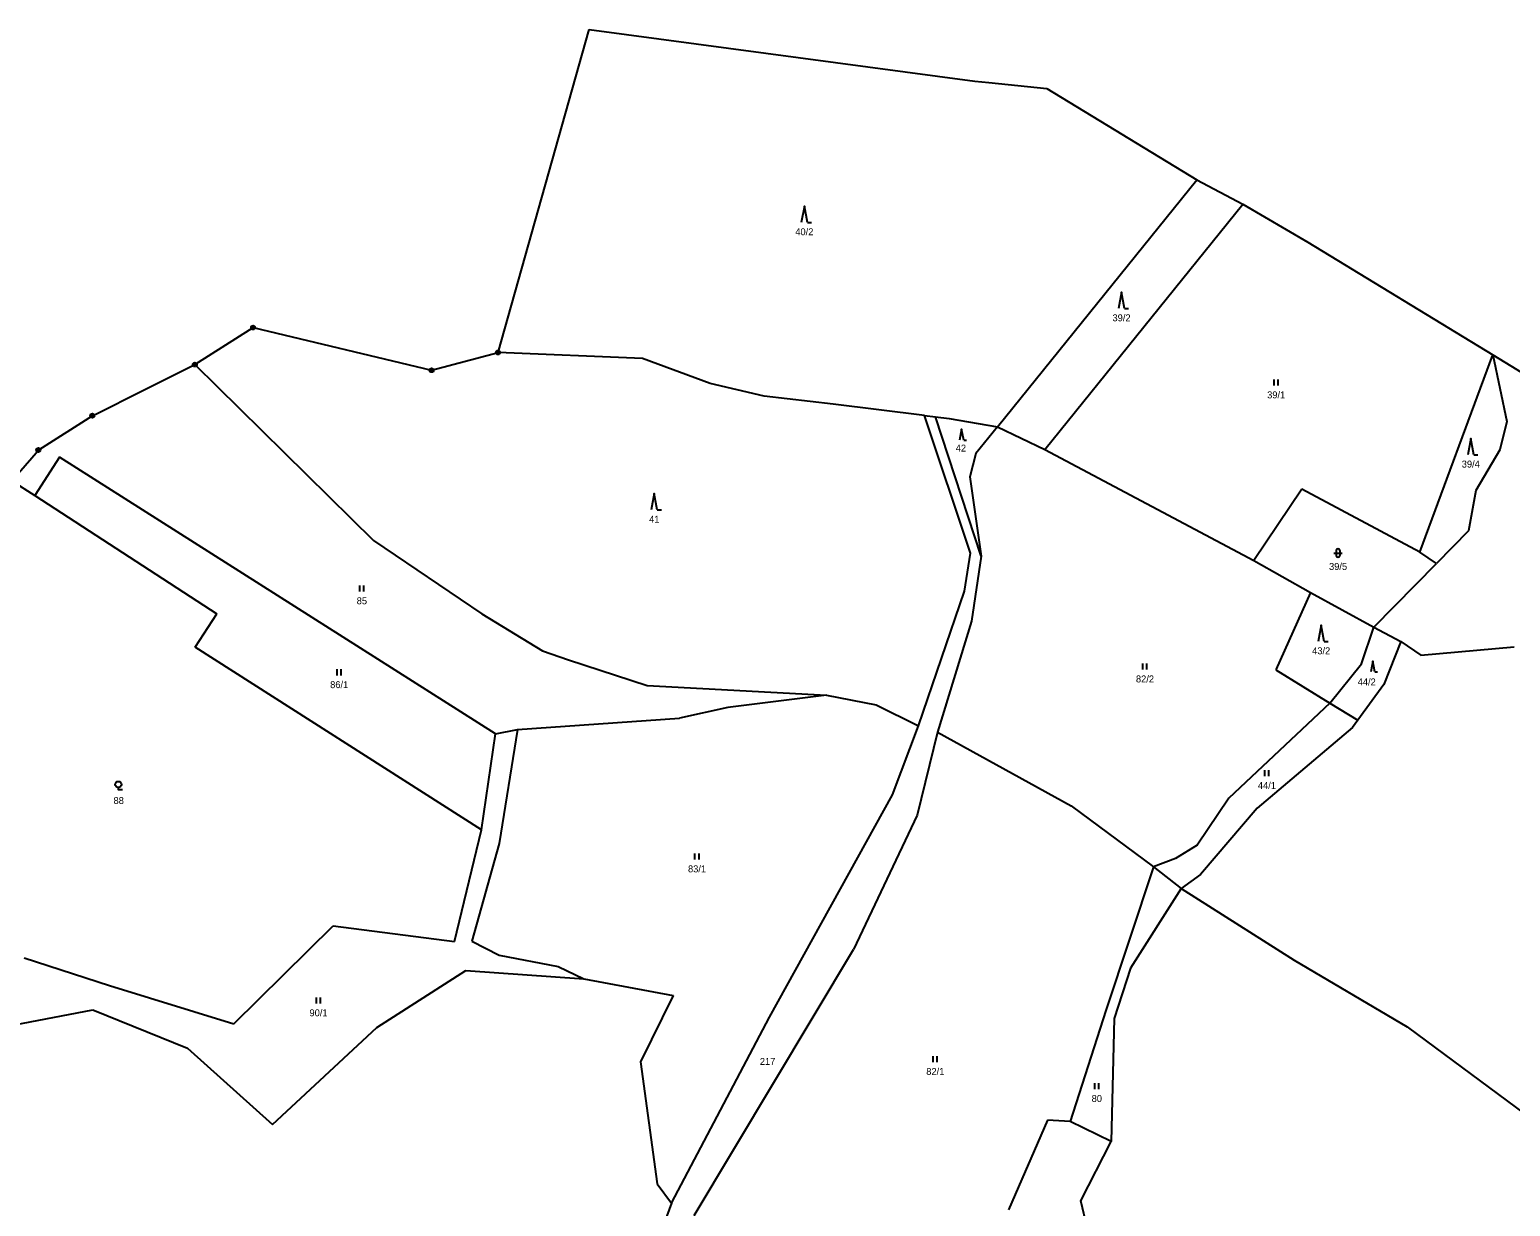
# Model space of a CAD drawing. Extents: x -601877 to -599786, y -1122905 to -1121218.
# Drawn here: x -601151.3 to -600789, y -1121506 to -1121217.8 of the extents above; entities that cross this region are included whole.
import ezdxf
from ezdxf.enums import TextEntityAlignment as Align

# ---------------------------------------------------------------- set-up
doc = ezdxf.new("R2010")
doc.units = 0
doc.header["$LTSCALE"] = 0.68
for name, color, linetype, lineweight in [('1', 7, 'Continuous', 25), ('3', 7, 'Continuous', 25), ('8', 7, 'Continuous', 25)]:
    doc.layers.add(name, color=color, linetype=linetype, lineweight=lineweight)
doc.layers.add('2', color=7, linetype='Continuous')

msp = doc.modelspace()

# ---------------------------------------------------------------- linework, layer by layer
at = {"layer": '1'}
for p, q in [((-601036.7, -1121296.89), (-601014.37, -1121217.82)), ((-601014.37, -1121217.82), (-600920.01, -1121230.46)), ((-600920.01, -1121230.46), (-600916.56, -1121230.81)), ((-600916.56, -1121230.81), (-600902.43, -1121232.26)), ((-600902.43, -1121232.26), (-600865.67, -1121254.58)), ((-600914.51, -1121315.06), (-600865.67, -1121254.58)), ((-600865.67, -1121254.58), (-600854.44, -1121260.58)), ((-600902.9, -1121320.63), (-600854.44, -1121260.58)), ((-600854.44, -1121260.58), (-600838.55, -1121269.88)), ((-600838.55, -1121269.88), (-600793.24, -1121297.49)), ((-601110.91, -1121299.84), (-601096.65, -1121290.78)), ((-601096.65, -1121290.78), (-601052.96, -1121301.23)), ((-601052.96, -1121301.23), (-601036.7, -1121296.89)), ((-601001.31, -1121298.32), (-601036.7, -1121296.89)), ((-600984.8, -1121304.47), (-601001.31, -1121298.32)), ((-600811.16, -1121345.81), (-600793.24, -1121297.49)), ((-600793.24, -1121297.49), (-600781.88, -1121304.42)), ((-600793.24, -1121297.49), (-600789.85, -1121313.79)), ((-601123.01, -1121305.88), (-601110.91, -1121299.84)), ((-601110.91, -1121299.84), (-601067.2, -1121342.91)), ((-601135.98, -1121312.36), (-601123.01, -1121305.88)), ((-600971.6, -1121307.55), (-600984.8, -1121304.47)), ((-600954.67, -1121309.58), (-600971.6, -1121307.55)), ((-600932.33, -1121312.32), (-600954.67, -1121309.58)), ((-601135.98, -1121312.36), (-601149.19, -1121320.77)), ((-600921.07, -1121346), (-600932.33, -1121312.32)), ((-600932.33, -1121312.32), (-600929.63, -1121312.64)), ((-600918.48, -1121346.72), (-600929.63, -1121312.64)), ((-600929.63, -1121312.64), (-600926.27, -1121313.06)), ((-600926.27, -1121313.06), (-600914.51, -1121315.06)), ((-600789.85, -1121313.79), (-600791.58, -1121320.71)), ((-600914.51, -1121315.06), (-600919.78, -1121321.62)), ((-600914.51, -1121315.06), (-600902.9, -1121320.63)), ((-601155.67, -1121328.31), (-601149.19, -1121320.77)), ((-600902.9, -1121320.63), (-600851.75, -1121347.86)), ((-600791.58, -1121320.71), (-600797.44, -1121330.68)), ((-601143.98, -1121322.5), (-601150.03, -1121331.89)), ((-601037.29, -1121390.27), (-601143.98, -1121322.5)), ((-600919.78, -1121321.62), (-600921.25, -1121327.37)), ((-601155.67, -1121328.31), (-601150.03, -1121331.89)), ((-600921.25, -1121327.37), (-600918.48, -1121346.72)), ((-601150.03, -1121331.89), (-601105.49, -1121360.84)), ((-600839.99, -1121330.39), (-600851.75, -1121347.86)), ((-600811.16, -1121345.81), (-600839.99, -1121330.39)), ((-600797.44, -1121330.68), (-600799.21, -1121340.56)), ((-601067.2, -1121342.91), (-601040.66, -1121360.85)), ((-600799.21, -1121340.56), (-600807.04, -1121348.57)), ((-600922.54, -1121355.35), (-600921.07, -1121346)), ((-600807.04, -1121348.57), (-600811.16, -1121345.81)), ((-600918.48, -1121346.72), (-600920.8, -1121362.67)), ((-600851.75, -1121347.86), (-600837.86, -1121355.67)), ((-600822.35, -1121364.11), (-600807.04, -1121348.57)), ((-600933.83, -1121388.31), (-600922.54, -1121355.35)), ((-600837.86, -1121355.67), (-600846.39, -1121374.58)), ((-600837.86, -1121355.67), (-600822.35, -1121364.11)), ((-601110.85, -1121369.06), (-601105.49, -1121360.84)), ((-601040.66, -1121360.85), (-601025.81, -1121369.95)), ((-600920.8, -1121362.67), (-600929.18, -1121389.84)), ((-600825.41, -1121373.12), (-600822.35, -1121364.11)), ((-600822.35, -1121364.11), (-600815.78, -1121367.65)), ((-600815.78, -1121367.65), (-600819.93, -1121378.17)), ((-600815.78, -1121367.65), (-600810.87, -1121371.03)), ((-601040.74, -1121413.79), (-601110.85, -1121369.06)), ((-601025.81, -1121369.95), (-601019.45, -1121372.13)), ((-600810.87, -1121371.03), (-600788.07, -1121368.99)), ((-601019.45, -1121372.13), (-601000.2, -1121378.44)), ((-600846.39, -1121374.58), (-600833.13, -1121382.72)), ((-600833.13, -1121382.72), (-600825.41, -1121373.12)), ((-601000.2, -1121378.44), (-600956.29, -1121380.82)), ((-600819.93, -1121378.17), (-600826.27, -1121386.93)), ((-600956.29, -1121380.82), (-600980.44, -1121383.82)), ((-600956.29, -1121380.82), (-600944.15, -1121383.17)), ((-600833.13, -1121382.72), (-600857.86, -1121406.05)), ((-600833.13, -1121382.72), (-600826.27, -1121386.93)), ((-601031.95, -1121389.18), (-600992.33, -1121386.46)), ((-600980.44, -1121383.82), (-600992.33, -1121386.46)), ((-600944.15, -1121383.17), (-600933.83, -1121388.31)), ((-601037.29, -1121390.27), (-601031.95, -1121389.18)), ((-601031.95, -1121389.18), (-601036.43, -1121417.12)), ((-600940.16, -1121405.16), (-600933.83, -1121388.31)), ((-600929.18, -1121389.84), (-600934.1, -1121410.17)), ((-600929.18, -1121389.84), (-600896.43, -1121407.89)), ((-600827.58, -1121388.74), (-600850.91, -1121408.44)), ((-600826.27, -1121386.93), (-600827.58, -1121388.74)), ((-601040.74, -1121413.79), (-601037.29, -1121390.27)), ((-600970.25, -1121459.63), (-600940.16, -1121405.16)), ((-600896.43, -1121407.89), (-600876.3, -1121422.85)), ((-600857.86, -1121406.05), (-600865.58, -1121417.55)), ((-600934.1, -1121410.17), (-600949.69, -1121443.09)), ((-600850.91, -1121408.44), (-600864.76, -1121424.67)), ((-601047.32, -1121441.15), (-601040.74, -1121413.79)), ((-601036.43, -1121417.12), (-601043.14, -1121441.02)), ((-600865.58, -1121417.55), (-600870.93, -1121420.75)), ((-600870.93, -1121420.75), (-600876.3, -1121422.85)), ((-600876.3, -1121422.85), (-600887.93, -1121458.01)), ((-600876.3, -1121422.85), (-600869.55, -1121428.17)), ((-600864.76, -1121424.67), (-600869.55, -1121428.17)), ((-600869.55, -1121428.17), (-600881.91, -1121447.64)), ((-600869.55, -1121428.17), (-600841.91, -1121445.69)), ((-601101.38, -1121461.28), (-601077.08, -1121437.24)), ((-601077.08, -1121437.24), (-601047.32, -1121441.15)), ((-601043.14, -1121441.02), (-601036.41, -1121444.46)), ((-601036.41, -1121444.46), (-601022.01, -1121447.21)), ((-600988.69, -1121508.19), (-600949.69, -1121443.09)), ((-601152.63, -1121445.09), (-601131.8, -1121451.85)), ((-601022.01, -1121447.21), (-601015.72, -1121450.29)), ((-600881.91, -1121447.64), (-600885.94, -1121459.96)), ((-600841.91, -1121445.69), (-600814.18, -1121462.04)), ((-601066.39, -1121462.14), (-601044.58, -1121448.25)), ((-601044.58, -1121448.25), (-601015.72, -1121450.29)), ((-601015.72, -1121450.29), (-600993.83, -1121454.36)), ((-601131.8, -1121451.85), (-601101.38, -1121461.28)), ((-600993.83, -1121454.36), (-601001.81, -1121470.54)), ((-601155.04, -1121461.52), (-601135.83, -1121457.82)), ((-601135.83, -1121457.82), (-601112.68, -1121467.24)), ((-600887.93, -1121458.01), (-600896.68, -1121485.23)), ((-601091.86, -1121485.95), (-601066.39, -1121462.14)), ((-600994.25, -1121505.16), (-600970.25, -1121459.63)), ((-600885.94, -1121459.96), (-600886.64, -1121490.06)), ((-600814.18, -1121462.04), (-600783.07, -1121485.12)), ((-601112.68, -1121467.24), (-601091.86, -1121485.95)), ((-601001.81, -1121470.54), (-600997.79, -1121500.49)), ((-600902.22, -1121484.89), (-600911.8, -1121506.8)), ((-600896.68, -1121485.23), (-600902.22, -1121484.89)), ((-600886.64, -1121490.06), (-600896.68, -1121485.23)), ((-600894.09, -1121504.65), (-600886.64, -1121490.06)), ((-600997.79, -1121500.49), (-600994.25, -1121505.16)), ((-600994.25, -1121505.16), (-601037.32, -1121622.62)), ((-600892.56, -1121511.17), (-600894.09, -1121504.65))]:
    msp.add_line(p, q, dxfattribs=at)
at = {"layer": '3'}
for p, q in [((-600960.99, -1121265.05), (-600959.994, -1121265.05)), ((-600883.37, -1121286.12), (-600882.374, -1121286.12)), ((-600846.781, -1121304.99), (-600846.781, -1121303.49)), ((-600845.78, -1121304.99), (-600845.78, -1121303.49)), ((-600922.748, -1121318.38), (-600922.08, -1121318.38)), ((-600797.9, -1121321.93), (-600796.904, -1121321.93)), ((-600997.72, -1121335.44), (-600996.724, -1121335.44)), ((-600832.131, -1121346.001), (-600830.129, -1121346.001)), ((-600831.631, -1121345.501), (-600831.631, -1121346.502)), ((-600830.629, -1121346.502), (-600830.629, -1121345.501)), ((-601070.531, -1121355.42), (-601070.531, -1121353.92)), ((-601069.53, -1121355.42), (-601069.53, -1121353.92)), ((-600834.51, -1121367.66), (-600833.514, -1121367.66)), ((-601076.081, -1121375.95), (-601076.081, -1121374.45)), ((-601075.08, -1121375.95), (-601075.08, -1121374.45)), ((-600878.891, -1121374.55), (-600878.891, -1121373.05)), ((-600877.89, -1121374.55), (-600877.89, -1121373.05)), ((-600822.118, -1121375.12), (-600821.45, -1121375.12)), ((-600849.051, -1121400.63), (-600849.051, -1121399.13)), ((-600848.05, -1121400.63), (-600848.05, -1121399.13)), ((-600988.511, -1121421.06), (-600988.511, -1121419.56)), ((-600987.51, -1121421.06), (-600987.51, -1121419.56)), ((-601081.141, -1121456.3), (-601081.141, -1121454.8)), ((-601080.14, -1121456.3), (-601080.14, -1121454.8)), ((-600930.201, -1121470.66), (-600930.201, -1121469.16)), ((-600929.2, -1121470.66), (-600929.2, -1121469.16)), ((-600890.681, -1121477.29), (-600890.681, -1121475.79)), ((-600889.68, -1121477.29), (-600889.68, -1121475.79))]:
    msp.add_line(p, q, dxfattribs=at)
for points in [[(-600960.99, -1121265.05), (-600961.74, -1121261.05), (-600962.49, -1121265.05)], [(-600883.37, -1121286.12), (-600884.12, -1121282.12), (-600884.87, -1121286.12)], [(-600922.748, -1121318.38), (-600923.25, -1121315.7), (-600923.752, -1121318.38)], [(-600797.9, -1121321.93), (-600798.65, -1121317.93), (-600799.4, -1121321.93)], [(-600997.72, -1121335.44), (-600998.47, -1121331.44), (-600999.22, -1121335.44)], [(-600834.51, -1121367.66), (-600835.26, -1121363.66), (-600836.01, -1121367.66)], [(-600822.118, -1121375.12), (-600822.62, -1121372.44), (-600823.122, -1121375.12)], [(-601129.63, -1121403.412), (-601129.63, -1121403.91), (-601128.629, -1121403.91)]]:
    msp.add_lwpolyline(points, dxfattribs=at)
msp.add_circle((-601129.6293, -1121402.6609), 0.75, dxfattribs=at)
for centre, start, end in [((-600831.13, -1121345.5009), 0, 180), ((-600831.13, -1121346.5009), 180, 359.98789)]:
    msp.add_arc(centre, 0.5, start, end, dxfattribs=at)
at = {"layer": '8'}
for centre, radius in [((-601096.65, -1121290.7799), 0.5), ((-601096.65, -1121290.7799), 0.0303), ((-601110.91, -1121299.8399), 0.5), ((-601036.7, -1121296.8899), 0.5), ((-601036.7, -1121296.8899), 0.0303), ((-601110.91, -1121299.8399), 0.0303), ((-601052.96, -1121301.2299), 0.5), ((-601052.96, -1121301.2299), 0.0303), ((-601135.98, -1121312.3599), 0.5), ((-601135.98, -1121312.3599), 0.0303), ((-601149.19, -1121320.7699), 0.5), ((-601149.19, -1121320.7699), 0.0303)]:
    msp.add_circle(centre, radius, dxfattribs=at)

# ---------------------------------------------------------------- texts
at = {"layer": '2'}
for s, p in [('40/2', (-600961.739, -1121268.175)), ('39/2', (-600884.119, -1121289.245)), ('39/1', (-600846.269, -1121308.115)), ('42', (-600923.429, -1121321.145)), ('39/4', (-600798.649, -1121325.055)), ('41', (-600998.469, -1121338.565)), ('39/5', (-600831.129, -1121350.125)), ('85', (-601070.019, -1121358.545)), ('43/2', (-600835.259, -1121370.785)), ('86/1', (-601075.569, -1121379.075)), ('82/2', (-600878.379, -1121377.675)), ('44/2', (-600824.119, -1121378.405)), ('44/1', (-600848.539, -1121403.755)), ('88', (-601129.529, -1121407.455)), ('83/1', (-600987.999, -1121424.185)), ('90/1', (-601080.629, -1121459.425)), ('217', (-600970.739, -1121471.325)), ('82/1', (-600929.689, -1121473.785)), ('80', (-600890.169, -1121480.415))]:
    msp.add_text(s, height=1.7, dxfattribs=at).set_placement(p, align=Align.CENTER)

doc.saveas('drawing.dxf')
